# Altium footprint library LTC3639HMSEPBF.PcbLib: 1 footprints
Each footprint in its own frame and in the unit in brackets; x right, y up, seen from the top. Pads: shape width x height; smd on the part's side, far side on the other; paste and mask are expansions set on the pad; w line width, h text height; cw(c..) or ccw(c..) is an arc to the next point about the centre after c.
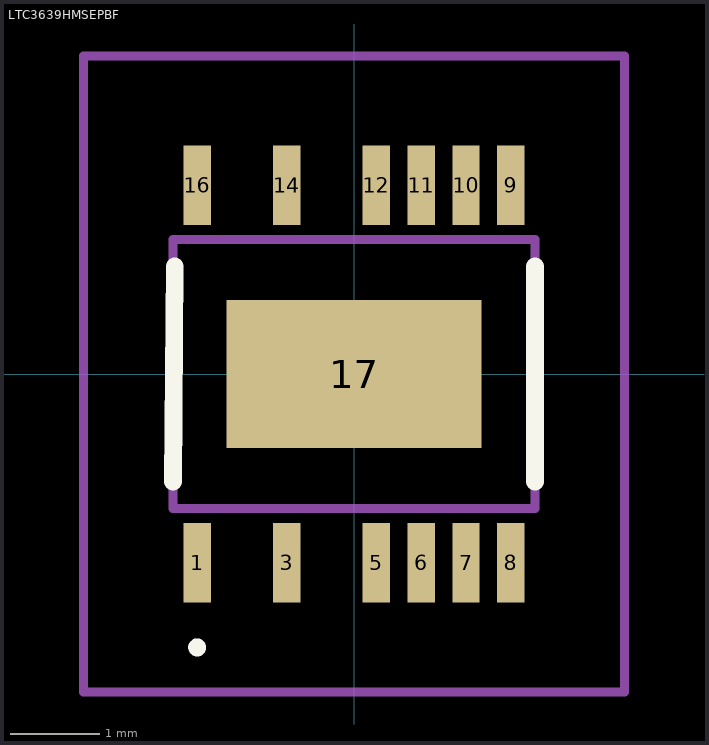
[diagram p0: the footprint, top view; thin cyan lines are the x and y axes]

## LTC3639HMSEPBF [mm]
pads (13):
  rect 0.305x0.889 smd: 1(-1.75,-2.106) 3(-0.75,-2.106) 5(0.25,-2.106) 6(0.75,-2.106) 7(1.25,-2.106) 8(1.75,-2.106) 9(1.75,2.106) 10(1.25,2.106) 11(0.75,2.106) 12(0.25,2.106) 14(-0.75,2.106) 16(-1.75,2.106)
  rect 2.845x1.651 smd: 17(0,0)
Top Overlay:
  lines w0.1: -1.75,-3.1 cw(c-1.75,-3.05) -1.75,-3 ; -1.75,-3.1 -1.75,-3.1 ; -1.75,-3.1 ccw(c-1.75,-3.05) -1.75,-3 ; -1.75,-3 -1.75,-3
  lines w0.2: -2.019,-1.2 -2,1.2 ; 2.019,-1.2 2.019,1.2
Mechanical 15:
  lines w0.1: -2.019,-1.5 2.019,-1.5 2.019,1.5 -2.019,1.5 -2.019,-1.5
Mechanical 20:
  lines w0.1: -3.019,-3.55 3.019,-3.55 3.019,3.55 -3.019,3.55 -3.019,-3.55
